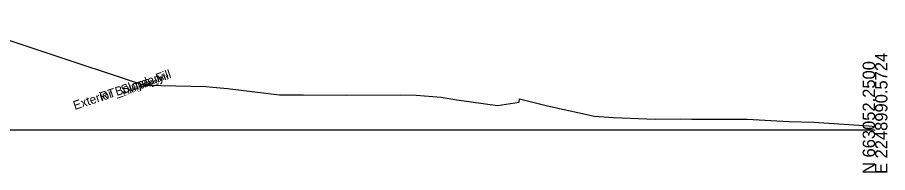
# Model space of a CAD drawing. Extents: x -26 to 2603, y -10 to 9566.
# Drawn here: x 1406.1 to 1602.8, y 2990.3 to 3025.5 of the extents above; entities that cross this region are included whole.
import ezdxf

# ---------------------------------------------------------------- set-up
doc = ezdxf.new("R2010")
doc.units = 0
for name, color, linetype in [('Exist Cross Section Cell', 7, 'Continuous'), ('Exist XS Ground Line', 7, 'Continuous'), ('Scratch_Level_9', 7, 'Continuous')]:
    doc.layers.add(name, color=color, linetype=linetype)

msp = doc.modelspace()

# ---------------------------------------------------------------- linework, layer by layer
at = {"layer": 'Exist Cross Section Cell'}
msp.add_line((1300, 3000), (1600, 3000), dxfattribs=at)
at = {"layer": 'Exist XS Ground Line'}
for p, q in [((1434.76, 3010.15), (1435.11, 3010.12)), ((1435.11, 3010.12), (1448.7, 3009.82)), ((1448.7, 3009.82), (1450.22, 3009.71)), ((1450.22, 3009.71), (1453.54, 3009.43)), ((1453.54, 3009.43), (1465.32, 3007.98)), ((1465.32, 3007.98), (1470.67, 3007.96)), ((1470.67, 3007.96), (1480.43, 3007.88)), ((1480.43, 3007.88), (1492.64, 3007.94)), ((1492.64, 3007.94), (1496.25, 3007.9)), ((1496.25, 3007.9), (1501.9, 3007.44)), ((1501.9, 3007.44), (1505.43, 3006.85)), ((1505.43, 3006.85), (1514.6, 3005.51)), ((1519.56, 3006.33), (1519.61, 3007.08)), ((1519.61, 3007.08), (1525.94, 3005.45)), ((1514.6, 3005.51), (1519.56, 3006.33)), ((1525.94, 3005.45), (1536.57, 3003.08)), ((1536.57, 3003.08), (1540.85, 3002.82)), ((1540.85, 3002.82), (1550.26, 3002.44)), ((1550.26, 3002.44), (1555.95, 3002.5)), ((1555.95, 3002.5), (1558.54, 3002.41)), ((1558.54, 3002.41), (1571.06, 3002.42)), ((1571.06, 3002.42), (1580.5, 3001.87)), ((1580.5, 3001.87), (1586.16, 3001.75)), ((1586.16, 3001.75), (1598.62, 3000.9)), ((1598.62, 3000.9), (1600, 3000.76))]:
    msp.add_line(p, q, dxfattribs=at)
msp.add_lwpolyline([(1388.62, 3025.53), (1434.76, 3010.15)], dxfattribs=at)

# ---------------------------------------------------------------- texts
at = {"layer": 'Exist Cross Section Cell'}
for s, p in [('E 2248990.5724', (1602.8, 2990)), ('N 663052.2500', (1600, 2990))]:
    msp.add_text(s, height=2.8, rotation=90, dxfattribs=at).set_placement(p)
at = {"layer": 'Scratch_Level_9'}
for s, height, rotation, p in [('Exterior Boundary', 2, 18.4332, (1419.07, 3004.52)), ('Exterior Boundary', 2, 18.4332, (1419.07, 3004.52)), ('RT_Slope_Fill', 2, 18.4332, (1425.07, 3006.52)), ('RT_Slope_Fill', 2, 18.4332, (1425.07, 3006.52)), ('Exterior Boundary', 1, 22.5575, (1430.17, 3007.63)), ('Exterior Boundary', 1, 22.5575, (1430.17, 3007.63)), ('RT_Slope_Fill', 1, 22.5575, (1431.58, 3008.21)), ('RT_Slope_Fill', 1, 22.5575, (1431.58, 3008.21))]:
    msp.add_text(s, height=height, rotation=rotation, dxfattribs=at).set_placement(p)

doc.saveas('drawing.dxf')
